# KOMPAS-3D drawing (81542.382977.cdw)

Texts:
  Крышка на обратный клапан
  материал:Текстолит,фторопласт
  * Уточнить по клапану.
  крышка должна туго "сидеть"
  на клапане.
Dimensions and other numbers on the sheet: 22; 18; 10; 3; 16; 1 штука; 17; 1:1; 1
